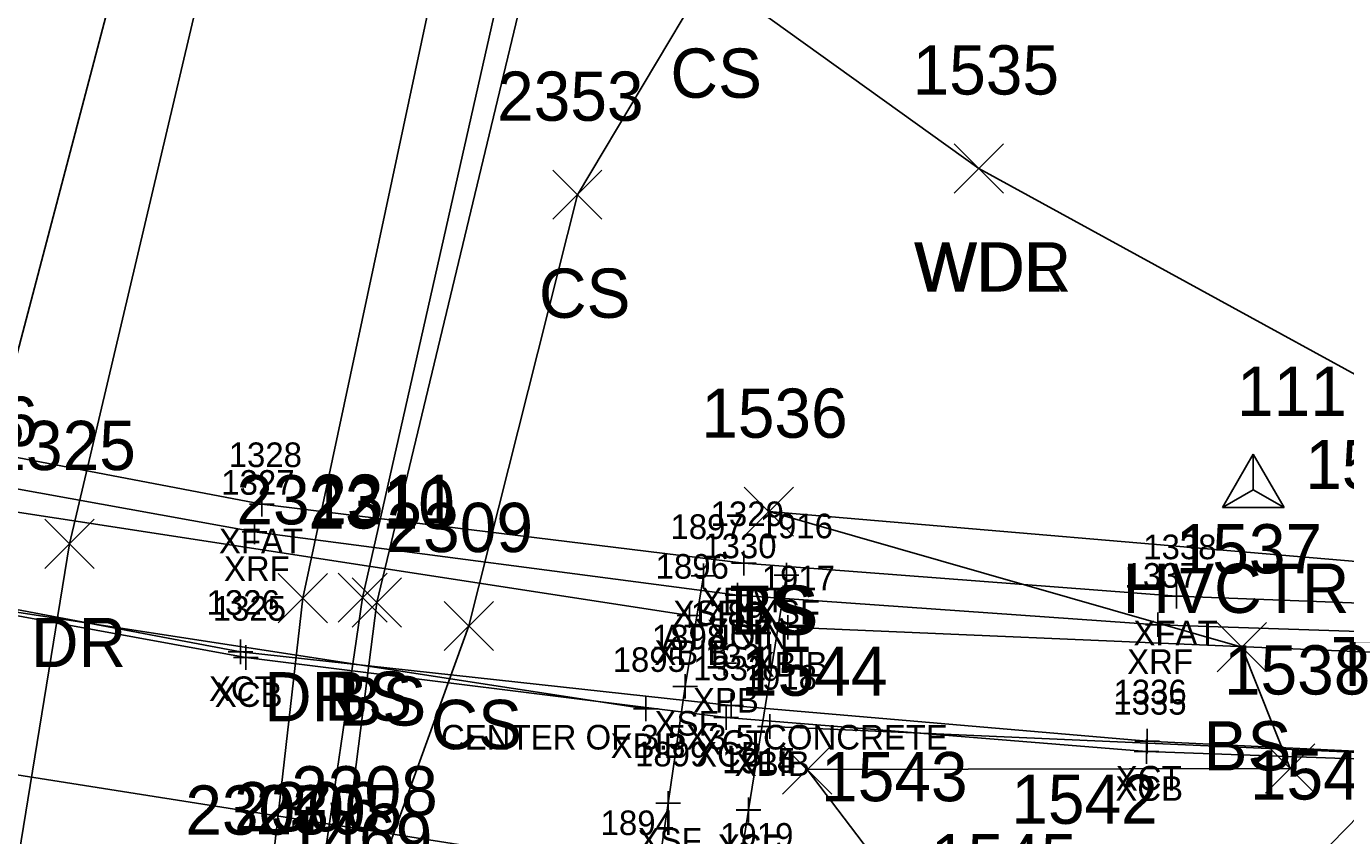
# Model space of a CAD drawing. Extents: x 1761340 to 1763889, y 696770 to 706023.
# Drawn here: x 1761657.7 to 1761711.3, y 700850 to 700882.9 of the extents above; entities that cross this region are included whole.
import ezdxf

# ---------------------------------------------------------------- set-up
doc = ezdxf.new("R2010")
doc.units = 0
for name, color, linetype in [('B_A', 7, 'Continuous'), ('B_C', 7, 'Continuous'), ('B_I', 7, 'Continuous'), ('B_TIC', 7, 'Continuous'), ('BB', 7, 'Continuous'), ('BDC', 7, 'Continuous'), ('BDEFAULT', 7, 'Continuous'), ('BF', 7, 'Continuous'), ('BR', 7, 'Continuous'), ('C_A', 7, 'Continuous'), ('C_I', 7, 'Continuous'), ('CPSM', 7, 'Continuous'), ('L_A', 7, 'Continuous'), ('L_I', 7, 'Continuous'), ('L_TIC', 7, 'Continuous'), ('LAWA', 7, 'Continuous'), ('LELB', 7, 'Continuous'), ('R_A', 7, 'Continuous'), ('R_I', 7, 'Continuous'), ('R_TIC', 7, 'Continuous'), ('RDP', 7, 'Continuous')]:
    doc.layers.add(name, color=color, linetype=linetype)

msp = doc.modelspace()

# ---------------------------------------------------------------- linework, layer by layer
at = {"layer": 'B_TIC'}
for p, q in [((1761667.291, 700863.505), (1761667.367, 700863.505)), ((1761666.991, 700862.382), (1761667.066, 700862.382)), ((1761686.865, 700861.108), (1761686.941, 700861.108)), ((1761685.229, 700860.586), (1761685.304, 700860.586)), ((1761688.597, 700860.614), (1761688.672, 700860.614)), ((1761686.607, 700859.803), (1761686.682, 700859.803)), ((1761704.429, 700859.764), (1761704.504, 700859.764)), ((1761684.657, 700858.973), (1761684.732, 700858.973)), ((1761688.65, 700858.499), (1761688.725, 700858.499)), ((1761703.669, 700858.606), (1761703.744, 700858.606)), ((1761666.423, 700857.506), (1761666.499, 700857.506)), ((1761666.644, 700857.269), (1761666.719, 700857.269)), ((1761686.061, 700857.037), (1761686.137, 700857.037)), ((1761684.477, 700856.102), (1761684.553, 700856.102)), ((1761682.882, 700855.189), (1761682.958, 700855.189)), ((1761686.353, 700855.322), (1761686.428, 700855.322)), ((1761686.146, 700854.84), (1761686.222, 700854.84)), ((1761687.922, 700854.467), (1761687.998, 700854.467)), ((1761703.245, 700853.873), (1761703.321, 700853.873)), ((1761703.212, 700853.454), (1761703.288, 700853.454)), ((1761683.796, 700851.352), (1761683.871, 700851.352)), ((1761687.047, 700851.073), (1761687.122, 700851.073)), ((1761687.053, 700851.093), (1761687.128, 700851.093))]:
    msp.add_line(p, q, dxfattribs=at)
for points in [[(1761667.288, 700863.005), (1761667.288, 700864.005)], [(1761666.788, 700863.505), (1761667.788, 700863.505)], [(1761666.987, 700861.882), (1761666.987, 700862.882)], [(1761666.487, 700862.382), (1761667.487, 700862.382)], [(1761686.862, 700860.608), (1761686.862, 700861.608)], [(1761685.225, 700860.086), (1761685.225, 700861.086)], [(1761686.362, 700861.108), (1761687.362, 700861.108)], [(1761688.593, 700860.114), (1761688.593, 700861.114)], [(1761684.725, 700860.586), (1761685.725, 700860.586)], [(1761686.603, 700859.303), (1761686.603, 700860.303)], [(1761688.093, 700860.614), (1761689.093, 700860.614)], [(1761704.425, 700859.264), (1761704.425, 700860.264)], [(1761686.103, 700859.803), (1761687.103, 700859.803)], [(1761703.925, 700859.764), (1761704.925, 700859.764)], [(1761684.653, 700858.473), (1761684.653, 700859.473)], [(1761684.153, 700858.973), (1761685.153, 700858.973)], [(1761688.646, 700857.999), (1761688.646, 700858.999)], [(1761703.665, 700858.106), (1761703.665, 700859.106)], [(1761688.146, 700858.499), (1761689.146, 700858.499)], [(1761703.165, 700858.606), (1761704.165, 700858.606)], [(1761666.42, 700857.006), (1761666.42, 700858.006)], [(1761666.64, 700856.769), (1761666.64, 700857.769)], [(1761665.92, 700857.506), (1761666.92, 700857.506)], [(1761666.14, 700857.269), (1761667.14, 700857.269)], [(1761686.058, 700856.537), (1761686.058, 700857.537)], [(1761684.474, 700855.602), (1761684.474, 700856.602)], [(1761685.558, 700857.037), (1761686.558, 700857.037)], [(1761683.974, 700856.102), (1761684.974, 700856.102)], [(1761682.879, 700854.689), (1761682.879, 700855.689)], [(1761686.349, 700854.822), (1761686.349, 700855.822)], [(1761682.379, 700855.189), (1761683.379, 700855.189)], [(1761685.849, 700855.322), (1761686.849, 700855.322)], [(1761686.143, 700854.34), (1761686.143, 700855.34)], [(1761687.919, 700853.967), (1761687.919, 700854.967)], [(1761685.643, 700854.84), (1761686.643, 700854.84)], [(1761687.419, 700854.467), (1761688.419, 700854.467)], [(1761703.242, 700853.373), (1761703.242, 700854.373)], [(1761702.742, 700853.873), (1761703.742, 700853.873)], [(1761703.209, 700852.954), (1761703.209, 700853.954)], [(1761702.709, 700853.454), (1761703.709, 700853.454)], [(1761683.792, 700850.852), (1761683.792, 700851.852)], [(1761683.292, 700851.352), (1761684.292, 700851.352)], [(1761687.043, 700850.573), (1761687.043, 700851.573)], [(1761687.049, 700850.593), (1761687.049, 700851.593)], [(1761686.543, 700851.073), (1761687.543, 700851.073)], [(1761686.549, 700851.093), (1761687.549, 700851.093)]]:
    msp.add_lwpolyline(points, dxfattribs=at)
at = {"layer": 'BB'}
for points in [[(1761645.991, 700864.914), (1761684.653, 700858.973)], [(1761645.428, 700860.945), (1761682.879, 700855.189)], [(1761688.646, 700858.499), (1761727.767, 700856.824)], [(1761644.371, 700854.559), (1761682.392, 700848.561)], [(1761687.919, 700854.467), (1761726.591, 700852.762)]]:
    msp.add_lwpolyline(points, dxfattribs=at)
at = {"layer": 'BDC'}
for points in [[(1761603.372, 700879.329), (1761602.459, 700873.228), (1761625.807, 700865.915), (1761643.998, 700861.743), (1761666.42, 700857.506), (1761686.349, 700855.322), (1761703.242, 700853.873), (1761720.711, 700853.034), (1761728.973, 700853.355), (1761729.967, 700859.215)], [(1761602.35, 700873.051), (1761625.784, 700865.689), (1761644.021, 700861.397), (1761666.64, 700857.269), (1761686.143, 700854.84), (1761703.209, 700853.454), (1761720.802, 700852.829), (1761729.026, 700852.764)]]:
    msp.add_lwpolyline(points, dxfattribs=at)
at = {"layer": 'BDEFAULT'}
for points in [[(1761685.225, 700860.586), (1761684.474, 700856.102), (1761683.792, 700851.352), (1761682.979, 700845.839), (1761682.993, 700845.76), (1761682.181, 700840.657), (1761682.206, 700840.63), (1761681.276, 700834.951), (1761681.277, 700834.942), (1761680.517, 700830.383)], [(1761683.781, 700830.194), (1761684.425, 700834.453), (1761684.443, 700834.498), (1761685.349, 700840.22), (1761685.351, 700840.274), (1761686.124, 700845.269), (1761686.141, 700845.32), (1761687.043, 700851.073), (1761687.049, 700851.093), (1761688.593, 700860.614)]]:
    msp.add_lwpolyline(points, dxfattribs=at)
at = {"layer": 'BF'}
msp.add_lwpolyline([(1761603.372, 700879.329), (1761627.262, 700871.889), (1761644.624, 700867.82), (1761667.288, 700863.505), (1761686.862, 700861.108), (1761704.425, 700859.764), (1761721.12, 700859.13), (1761729.967, 700859.215)], dxfattribs=at)
at = {"layer": 'BR'}
msp.add_lwpolyline([(1761603.404, 700877.977), (1761626.827, 700870.765), (1761644.368, 700866.459), (1761666.987, 700862.382), (1761686.603, 700859.803), (1761703.665, 700858.606), (1761720.831, 700858.025), (1761729.539, 700857.943)], dxfattribs=at)
at = {"layer": 'CPSM'}
for p, q in [((1761706.295, 700863.362), (1761707.545, 700865.528)), ((1761708.795, 700863.362), (1761707.545, 700865.528)), ((1761707.545, 700864.084), (1761707.545, 700865.528)), ((1761706.295, 700863.362), (1761707.545, 700864.084)), ((1761707.545, 700864.084), (1761707.545, 700864.084)), ((1761707.545, 700864.084), (1761708.795, 700863.362)), ((1761706.295, 700863.362), (1761708.795, 700863.362))]:
    msp.add_line(p, q, dxfattribs=at)
at = {"layer": 'L_TIC'}
for points in [[(1761695.403, 700876.132), (1761697.403, 700878.132)], [(1761697.403, 700876.132), (1761695.403, 700878.132)], [(1761695.403, 700876.132), (1761697.403, 700878.132)], [(1761697.403, 700876.132), (1761695.403, 700878.132)], [(1761679.099, 700875.066), (1761681.099, 700877.066)], [(1761681.099, 700875.066), (1761679.099, 700877.066)], [(1761686.875, 700862.195), (1761688.875, 700864.195)], [(1761688.875, 700862.195), (1761686.875, 700864.195)], [(1761686.875, 700862.195), (1761688.875, 700864.195)], [(1761688.875, 700862.195), (1761686.875, 700864.195)], [(1761670.381, 700858.702), (1761672.381, 700860.702)], [(1761672.381, 700858.702), (1761670.381, 700860.702)], [(1761670.954, 700858.509), (1761672.954, 700860.509)], [(1761672.954, 700858.509), (1761670.954, 700860.509)], [(1761674.695, 700857.554), (1761676.695, 700859.554)], [(1761676.695, 700857.554), (1761674.695, 700859.554)], [(1761706.085, 700856.688), (1761708.085, 700858.688)], [(1761708.085, 700856.688), (1761706.085, 700858.688)], [(1761688.436, 700851.719), (1761690.436, 700853.719)], [(1761690.436, 700851.719), (1761688.436, 700853.719)], [(1761688.436, 700851.719), (1761690.436, 700853.719)], [(1761690.436, 700851.719), (1761688.436, 700853.719)], [(1761708.046, 700851.771), (1761710.046, 700853.771)], [(1761710.046, 700851.771), (1761708.046, 700853.771)]]:
    msp.add_lwpolyline(points, dxfattribs=at)
at = {"layer": 'LAWA'}
for points in [[(1761696.403, 700877.132), (1761722.268, 700862.97), (1761723.716, 700872.008), (1761721.644, 700895.629), (1761726.277, 700910.333), (1761732.763, 700919.168), (1761734.997, 700942.591)], [(1761696.403, 700877.132), (1761685.438, 700885.001)]]:
    msp.add_lwpolyline(points, dxfattribs=at)
at = {"layer": 'LELB'}
for points in [[(1761681.301, 700585.517), (1761671.929, 700613.506), (1761667.591, 700648.271), (1761662.956, 700684.404), (1761660.968, 700720.859), (1761660.494, 700762.081), (1761662.811, 700791.593), (1761666.165, 700822.147), (1761669.086, 700835.752), (1761669.554, 700847.216), (1761671.381, 700859.702), (1761679.654, 700896.376), (1761688.232, 700933.044), (1761696.404, 700960.959), (1761706.351, 700997.906), (1761723.358, 701026.155)], [(1761684.453, 700586.471), (1761674.154, 700613.84), (1761669.556, 700648.243), (1761665.944, 700684.581), (1761663.689, 700720.734), (1761662.667, 700762.265), (1761665.109, 700791.249), (1761666.952, 700822.175), (1761669.965, 700835.611), (1761670.376, 700847.091), (1761671.954, 700859.509), (1761680.672, 700895.811), (1761689.739, 700932.613), (1761697.717, 700961.083), (1761707.94, 700997.332), (1761724.654, 701022.108)], [(1761650.668, 700568.581), (1761653.72, 700589.345), (1761656.228, 700611.846), (1761650.783, 700645.878), (1761646.693, 700682.268), (1761643.965, 700721.139), (1761646.185, 700763.151), (1761649.001, 700791.974), (1761651.08, 700826.684), (1761655.56, 700862.863), (1761665.437, 700900.351), (1761673.527, 700937.717), (1761682.384, 700964.347), (1761693.002, 701008.082), (1761690.127, 701015.338), (1761683.006, 701019.111)], [(1761685.438, 700885.001), (1761680.099, 700876.066)], [(1761671.82, 700847.861), (1761675.695, 700858.554), (1761680.099, 700876.066)], [(1761687.875, 700863.195), (1761712.355, 700861.111), (1761714.798, 700853.885), (1761709.534, 700848.506), (1761700.41, 700847.52), (1761692.689, 700848.437), (1761689.436, 700852.719)], [(1761687.875, 700863.195), (1761707.085, 700857.688), (1761709.046, 700852.771), (1761689.436, 700852.719)]]:
    msp.add_lwpolyline(points, dxfattribs=at)
at = {"layer": 'R_TIC'}
for points in [[(1761658.48, 700860.884), (1761660.48, 700862.884)], [(1761660.48, 700860.884), (1761658.48, 700862.884)], [(1761667.947, 700858.679), (1761669.947, 700860.679)], [(1761669.947, 700858.679), (1761667.947, 700860.679)]]:
    msp.add_lwpolyline(points, dxfattribs=at)
at = {"layer": 'RDP'}
for points in [[(1761671.259, 700538.434), (1761661.644, 700574.622), (1761657.605, 700611.792), (1761653.176, 700645.742), (1761649.934, 700682.027), (1761646.901, 700721.235), (1761649.099, 700763.058), (1761651.354, 700791.608), (1761653.655, 700826.216), (1761659.48, 700861.884), (1761668.314, 700899.372), (1761676.768, 700936.595), (1761684.872, 700963.935), (1761695.512, 701007.432), (1761695.754, 701009.139), (1761702.957, 701038.717), (1761714.691, 701083.389), (1761730.248, 701133.725)], [(1761685.903, 700541.843), (1761678.398, 700578.094), (1761669.593, 700613.166), (1761665.81, 700647.626), (1761660.309, 700684.319), (1761659.551, 700721.027), (1761658.733, 700762.092), (1761660.802, 700791.687), (1761663.623, 700822.45), (1761666.152, 700836.338), (1761667.517, 700847.08), (1761668.947, 700859.679), (1761676.875, 700896.799), (1761686.16, 700933.202), (1761693.935, 700961.975), (1761704.585, 700998.319), (1761705.06, 700999.037), (1761715.839, 701034.881), (1761727.081, 701077.741), (1761742.289, 701129.681)]]:
    msp.add_lwpolyline(points, dxfattribs=at)

# ---------------------------------------------------------------- texts
at = {"layer": 'B_A'}
for s, p in [('XFAT', (1761665.544, 700861.505)), ('XRF', (1761665.747, 700860.382)), ('XFAT', (1761685.118, 700859.108)), ('XSF', (1761683.985, 700858.586)), ('XSF', (1761687.353, 700858.614)), ('XRF', (1761685.363, 700857.803)), ('XFAT', (1761702.681, 700857.764)), ('XBIB', (1761683.224, 700856.973)), ('XRF', (1761702.425, 700856.606)), ('XBIB', (1761687.217, 700856.499)), ('XCT', (1761665.14, 700855.506)), ('XCB', (1761665.376, 700855.269)), ('XPB', (1761684.794, 700855.037)), ('XSF', (1761683.234, 700854.102)), ('XBIB', (1761681.45, 700853.189)), ('XCB', (1761684.879, 700852.84)), ('XCT', (1761685.07, 700853.322)), ('XBIB', (1761686.49, 700852.467)), ('XCT', (1761701.962, 700851.873)), ('XCB', (1761701.945, 700851.454)), ('XSF', (1761682.552, 700849.352)), ('XSF', (1761685.803, 700849.073)), ('XSF', (1761685.809, 700849.093))]:
    msp.add_text(s, height=1, dxfattribs=at).set_placement(p)
at = {"layer": 'B_C'}
for s, p in [('AT JOINT', (1761683.535, 700857.608)), ('CENTER OF 3.5X3.5 CONCRETE', (1761674.562, 700853.537))]:
    msp.add_text(s, height=1, dxfattribs=at).set_placement(p)
at = {"layer": 'B_I'}
for s, p in [('1328', (1761665.941, 700865.005)), ('1327', (1761665.641, 700863.882)), ('1329', (1761685.512, 700862.608)), ('1897', (1761683.879, 700862.086)), ('1916', (1761687.503, 700862.114)), ('1330', (1761685.213, 700861.303)), ('1338', (1761703.079, 700861.264)), ('1896', (1761683.279, 700860.473)), ('1917', (1761687.584, 700859.999)), ('1337', (1761702.319, 700860.106)), ('1326', (1761665.046, 700859.006)), ('1325', (1761665.294, 700858.769)), ('1489', (1761684.708, 700858.537)), ('1898', (1761683.127, 700857.602)), ('1895', (1761681.533, 700856.689)), ('1331', (1761685.286, 700856.822)), ('1332', (1761684.797, 700856.34)), ('1918', (1761686.856, 700855.967)), ('1335', (1761701.863, 700854.954)), ('1336', (1761701.868, 700855.373)), ('1899', (1761682.442, 700852.852)), ('1914', (1761685.981, 700852.573)), ('1915', (1761685.986, 700852.593)), ('1894', (1761681.045, 700850.061)), ('1919', (1761685.896, 700849.55))]:
    msp.add_text(s, height=1, dxfattribs=at).set_placement(p)
at = {"layer": 'C_A'}
msp.add_text('HVCTRL', height=2, dxfattribs=at).set_placement((1761702.238, 700859.084))
at = {"layer": 'C_I'}
msp.add_text('111', height=2, dxfattribs=at).set_placement((1761706.884, 700867.084))
at = {"layer": 'L_A'}
for s, p in [('CS', (1761683.879, 700880.001)), ('WDR', (1761693.765, 700872.132)), ('WDL', (1761693.82, 700872.132)), ('CS', (1761678.54, 700871.066)), ('TS', (1761686.285, 700858.195)), ('BS', (1761686.316, 700858.195)), ('TS', (1761710.764, 700856.111)), ('BS', (1761669.822, 700854.702)), ('BS', (1761670.395, 700854.509)), ('CS', (1761674.136, 700853.554)), ('BS', (1761705.526, 700852.688))]:
    msp.add_text(s, height=2, dxfattribs=at).set_placement(p)
at = {"layer": 'L_I'}
for s, p in [('1535', (1761693.71, 700880.132)), ('1535', (1761693.71, 700880.132)), ('2353', (1761676.839, 700879.066)), ('2326', (1761652.246, 700865.863)), ('1536', (1761685.127, 700866.195)), ('1536', (1761685.127, 700866.195)), ('1539', (1761709.654, 700864.111)), ('2310', (1761669.175, 700862.509)), ('2311', (1761669.255, 700862.702)), ('2309', (1761672.349, 700861.554)), ('1537', (1761704.393, 700860.688)), ('1544', (1761686.743, 700855.719)), ('1544', (1761686.743, 700855.719)), ('1538', (1761706.353, 700855.771)), ('1543', (1761689.996, 700851.437)), ('1541', (1761707.408, 700851.506)), ('2308', (1761668.481, 700850.861)), ('2306', (1761666.16, 700850.216)), ('1542', (1761697.718, 700850.52)), ('2305', (1761667.038, 700850.091)), ('1469', (1761668.262, 700848.965)), ('1545', (1761694.448, 700848.109))]:
    msp.add_text(s, height=2, dxfattribs=at).set_placement(p)
at = {"layer": 'R_A'}
for p in [(1761657.913, 700856.884), (1761667.38, 700854.679)]:
    msp.add_text('DR', height=2, dxfattribs=at).set_placement(p)
at = {"layer": 'R_I'}
for s, p in [('2325', (1761656.22, 700864.884)), ('2312', (1761666.254, 700862.679)), ('2307', (1761664.179, 700850.08))]:
    msp.add_text(s, height=2, dxfattribs=at).set_placement(p)

doc.saveas('drawing.dxf')
